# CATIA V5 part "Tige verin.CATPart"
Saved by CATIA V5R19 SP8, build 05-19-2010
Part number: Tige verin
Bounding box of the stored display mesh (mm): x -125 to 627.5, y -125 to 1900, z -125 to 125
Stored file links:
  C:\Users\rcousturie\Desktop\EU_thinkMotion\iao\IAO_MMS_Groupe1\flacan\flacan\flacan\Tige verin.CATPart
  C:\Documents and Settings\flacan\Bureau\Piece IAO\Assemblage.CATProduct
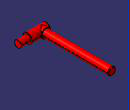
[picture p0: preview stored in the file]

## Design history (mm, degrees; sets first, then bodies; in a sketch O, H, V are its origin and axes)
External parameters (linked from other documents)
  `External.Diamètre interne verin` = 200 mm
Body1 (main body)
  Sketch1 on zx-plane, origin (0, 0, 0), H (-1, 0, 0), V (0, 0, 1)
    circle A1 centre (0, 0) radius 100
    radius A1 = 100 {= `External.Diamètre interne verin` /2}
  Pad1: profile Sketch1, direction (0, 1, 0), length 1900
  Sketch2 on yz-plane, origin (0, 0, 0), H (0, 1, 0), V (0, 0, 1)
    circle A1 centre (0, 0) radius 125
    radius A1 = 125
  Pad2: profile Sketch2, direction (1, 0, 0), length 365, opposite side length 125
  Sketch3 on end face of Pad2, origin (365, 0, 0), H (0, 1, 0), V (0, 0, 1)
    circle A1 centre (0, 0) radius 87.5
    radius A1 = 87.5
  Pad3: profile Sketch3, direction (1, 0, 0), length 262.5
  Sketch4 on zx-plane, origin (0, 0, 0), H (-1, 0, 0), V (0, 0, 1)
    circle A1 centre (0, 0) radius 125
    radius A1 = 125
  Pad4: profile Sketch4, direction (0, 1, 0), length 125
  Chamfer1: length 20, angle 45, on edge [face of Pad1 from Sketch1.A1 | end face of Pad1]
